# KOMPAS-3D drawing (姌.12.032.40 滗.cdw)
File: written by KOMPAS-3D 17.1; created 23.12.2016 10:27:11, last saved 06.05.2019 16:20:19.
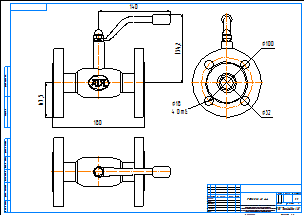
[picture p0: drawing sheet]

Sheet 1: A2, landscape

Title block, sheet 1: name: КШ.12.032.40 фф; material: Внимание! Данный продукт является объектом авторского права ООО «Торговый Дом АДЛ». / Запрещается изменение, копирование, распространение / (в том числе путем копирования на другие сайты и ресурсы в Интернете) / или любое иное использование информации и объектов без предварительного / согласия правообладателя (ООО «Торговый Дом АДЛ»).; sheets: 1; organisation: ООО "Торговый дом АДЛ"; sheet format: A2; stored path: C:\Users\tra\Desktop\2д чертежи\Шаровые краны БИВАЛ\КШ_Бивал_серия_11_12\KOMPAS_2D\КШ.12.032.40 фф.cdw

Views: Вид 1, Проекционный вид 2, Проекционный вид 3
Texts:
  Klimkovich
  ADL
Dimensions and other numbers on the sheet: 180; 140; 134,2; 67,5; 100; 32; 18; 4 Отв.; 1:1; 1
